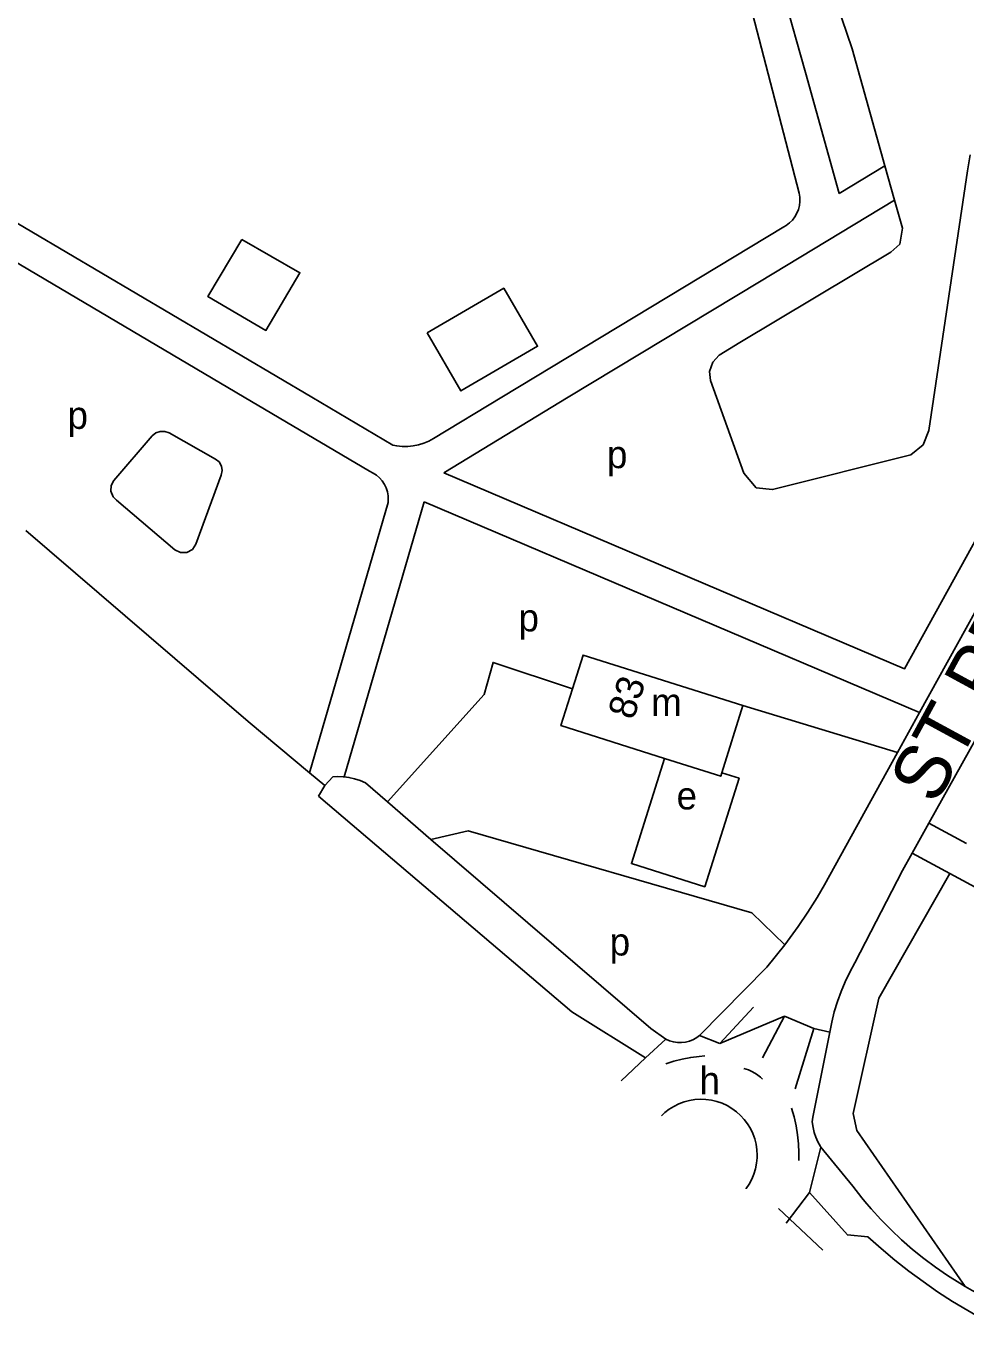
# Model space of a CAD drawing. Extents: x 162804 to 165059, y 381530 to 382901.
# Drawn here: x 163167.6 to 163304.5, y 381614.3 to 381804.1 of the extents above; entities that cross this region are included whole.
import ezdxf

# ---------------------------------------------------------------- set-up
doc = ezdxf.new("R2010")
doc.units = 0
for name, color, linetype in [('BLT_Basislijn', 7, 'Continuous'), ('BLT_Bebouwing', 7, 'Continuous'), ('BLT_Centroide', 7, 'Continuous'), ('BLT_Huisnummer', 7, 'Continuous'), ('BLT_Straatnaam_hoofdweg', 7, 'Continuous'), ('BLT_Vlakafsluiter', 7, 'Continuous')]:
    doc.layers.add(name, color=color, linetype=linetype)

msp = doc.modelspace()

# ---------------------------------------------------------------- linework, layer by layer
at = {"layer": 'BLT_Basislijn'}
for p, q in [((163269.68, 381838.14), (163279.75, 381802.12)), ((163280.18, 381779.7), (163265.55, 381836.33)), ((163279.75, 381802.12), (163281.1, 381797.3)), ((163281.1, 381797.3), (163286.03, 381779.66)), ((163148.62, 381785.81), (163209.2, 381750)), ((163292.69, 381783.69), (163286.03, 381779.66)), ((163292.69, 381783.69), (163294.09, 381778.69)), ((163146.08, 381781.51), (163199.38, 381750)), ((163294.09, 381778.69), (163274.43, 381766.82)), ((163277.97, 381774.82), (163236.9, 381750)), ((163274.43, 381766.82), (163246.57, 381750)), ((163199.38, 381750), (163217.63, 381739.21)), ((163209.2, 381750), (163221.04, 381743)), ((163236.9, 381750), (163226.94, 381743.99)), ((163246.57, 381750), (163228.44, 381738.97)), ((163297.74, 381704.09), (163318.64, 381741.96)), ((163220.33, 381734.65), (163208.89, 381695.28)), ((163225.56, 381734.76), (163213.93, 381694.7)), ((163199.95, 381702.79), (163167.55, 381730.6)), ((163316.35, 381718.94), (163299.08, 381687.95)), ((163271.98, 381705.1), (163294.51, 381698.24)), ((163294.51, 381698.24), (163297.74, 381704.09)), ((163199.95, 381702.79), (163208.89, 381695.28)), ((163283.87, 381678.96), (163294.51, 381698.24)), ((163208.89, 381695.28), (163211.1, 381693.42)), ((163212.26, 381694.71), (163211.1, 381693.42)), ((163220.22, 381691.07), (163217.03, 381693.81)), ((163211.1, 381693.42), (163210.2, 381691.87)), ((163226.57, 381685.6), (163220.22, 381691.07)), ((163299.08, 381687.95), (163296.65, 381683.58)), ((163299.08, 381687.95), (163304.57, 381685)), ((163296.65, 381683.58), (163302.14, 381680.63)), ((163302.14, 381680.63), (163291.79, 381662.45)), ((163302.14, 381680.63), (163307.1, 381677.96)), ((163275.49, 381666.96), (163278.12, 381670.25)), ((163265.68, 381657.02), (163275.49, 381666.96)), ((163291.79, 381662.45), (163288.06, 381645.69)), ((163273.55, 381661.15), (163268.65, 381655.86)), ((163278.07, 381659.86), (163274.84, 381653.79)), ((163282.32, 381658.05), (163279.62, 381649.27)), ((163284.65, 381657.53), (163282.2, 381645.14)), ((163261.26, 381646.29), (163260.62, 381645.79)), ((163261.95, 381646.71), (163261.26, 381646.29)), ((163262.67, 381647.07), (163261.95, 381646.71)), ((163263.43, 381647.36), (163262.67, 381647.07)), ((163264.21, 381647.56), (163263.43, 381647.36)), ((163265, 381647.7), (163264.21, 381647.56)), ((163265.81, 381647.74), (163265, 381647.7)), ((163266.62, 381647.72), (163265.81, 381647.74)), ((163267.42, 381647.61), (163266.62, 381647.72)), ((163268.2, 381647.42), (163267.42, 381647.61)), ((163268.97, 381647.16), (163268.2, 381647.42)), ((163269.7, 381646.82), (163268.97, 381647.16)), ((163270.4, 381646.41), (163269.7, 381646.82)), ((163271.05, 381645.93), (163270.4, 381646.41)), ((163260.62, 381645.79), (163260.15, 381645.35)), ((163271.65, 381645.4), (163271.05, 381645.93)), ((163272.2, 381644.8), (163271.65, 381645.4)), ((163272.68, 381644.15), (163272.2, 381644.8)), ((163282.2, 381645.14), (163282.1, 381644.44)), ((163288.06, 381645.69), (163288.59, 381643.17)), ((163273.1, 381643.46), (163272.68, 381644.15)), ((163273.45, 381642.73), (163273.1, 381643.46)), ((163273.72, 381641.97), (163273.45, 381642.73)), ((163288.59, 381643.17), (163304.39, 381620.46)), ((163273.92, 381641.19), (163273.72, 381641.97)), ((163274.04, 381640.39), (163273.92, 381641.19)), ((163283.36, 381640.75), (163288, 381635.07)), ((163274, 381638.41), (163274.07, 381639.22)), ((163274.08, 381639.59), (163274.04, 381640.39)), ((163274.07, 381639.22), (163274.08, 381639.59)), ((163273.3, 381636.1), (163273.61, 381636.85)), ((163273.61, 381636.85), (163273.84, 381637.62)), ((163273.84, 381637.62), (163274, 381638.41)), ((163272.47, 381634.72), (163272.92, 381635.39)), ((163272.92, 381635.39), (163273.3, 381636.1)), ((163272.46, 381634.7), (163272.47, 381634.72)), ((163277.16, 381631.84), (163283.62, 381625.78))]:
    msp.add_line(p, q, dxfattribs=at)
for points in [[(163285.66, 381807.29), (163287.92, 381800.74), (163292.69, 381783.69)], [(163294.09, 381778.69), (163295.22, 381774.64), (163294.83, 381772.31), (163293.55, 381771.11), (163271.56, 381757.97), (163268.52, 381756.15), (163267.6, 381755.11), (163267.13, 381753.75), (163267.28, 381752.42), (163272.13, 381738.94), (163273.95, 381736.81), (163276.33, 381736.55), (163296.44, 381741.63), (163298.25, 381743.08), (163299.1, 381745.15), (163304.71, 381782.98), (163305.09, 381785.3)], [(163228.44, 381738.97), (163295.54, 381710.45), (163314.26, 381744.38), (163334.75, 381781.49)], [(163280.18, 381779.7), (163280.28, 381779.12), (163280.29, 381778.52), (163280.23, 381777.93), (163280.08, 381777.35), (163279.86, 381776.8), (163279.57, 381776.28), (163279.21, 381775.81), (163278.79, 381775.39), (163278.32, 381775.03), (163277.97, 381774.82)], [(163226.94, 381743.99), (163226.24, 381743.6), (163225.51, 381743.29), (163224.75, 381743.06), (163223.97, 381742.9), (163223.18, 381742.82), (163222.38, 381742.82), (163221.59, 381742.9), (163221.04, 381743)], [(163217.63, 381739.21), (163218.16, 381738.96), (163218.65, 381738.63), (163219.09, 381738.25), (163219.48, 381737.8), (163219.8, 381737.31), (163220.06, 381736.78), (163220.24, 381736.22), (163220.34, 381735.64), (163220.36, 381735.05), (163220.33, 381734.65)], [(163225.56, 381734.76), (163297.74, 381704.09)], [(163247.18, 381707.51), (163235.61, 381711.37), (163234.32, 381706.72), (163220.22, 381691.07)], [(163260.59, 381697.37), (163255.76, 381682.07), (163266.45, 381678.7), (163271.44, 381694.51), (163268.93, 381695.28)], [(163213.93, 381694.7), (163213.78, 381694.72), (163212.94, 381694.75), (163212.26, 381694.71)], [(163217.03, 381693.81), (163216.26, 381694.15), (163215.45, 381694.42), (163214.62, 381694.61), (163213.93, 381694.7)], [(163210.2, 381691.87), (163247.1, 381660.5), (163257.81, 381653.79)], [(163226.57, 381685.6), (163232.01, 381686.84), (163273.29, 381674.89), (163278.12, 381670.25)], [(163260.78, 381656.5), (163258.58, 381658.05), (163226.57, 381685.6)], [(163296.65, 381683.58), (163295.23, 381681.05), (163288.32, 381667.59)], [(163278.12, 381670.25), (163280.06, 381672.91), (163281.46, 381674.99), (163282.79, 381677.11), (163283.87, 381678.96)], [(163288.32, 381667.59), (163287.57, 381666.24), (163286.9, 381664.85), (163286.29, 381663.42), (163285.76, 381661.97), (163285.31, 381660.49), (163284.93, 381658.99), (163284.65, 381657.53)], [(163257.81, 381653.79), (163260.78, 381656.5)], [(163260.78, 381656.5), (163261.32, 381656.26), (163261.89, 381656.09), (163262.47, 381656), (163263.07, 381655.99), (163263.65, 381656.06), (163264.23, 381656.21), (163264.78, 381656.43), (163265.29, 381656.73), (163265.68, 381657.02)], [(163260.78, 381652.89), (163261.96, 381653.28), (163263.17, 381653.59), (163264.4, 381653.83), (163265.64, 381653.99), (163266.45, 381654.05)], [(163272.13, 381652.24), (163272.79, 381652.03), (163273.41, 381651.74), (163274, 381651.39), (163274.55, 381650.97), (163274.84, 381650.69)], [(163279.1, 381646.43), (163279.47, 381645.16), (163279.76, 381643.87), (163279.97, 381642.57), (163280.1, 381641.25), (163280.15, 381639.93), (163280.13, 381638.82)], [(163282.1, 381644.44), (163282.24, 381643.65), (163282.39, 381642.92), (163282.61, 381642.21), (163282.91, 381641.52), (163283.28, 381640.87), (163283.36, 381640.75)], [(163283.36, 381640.75), (163281.68, 381634.17)], [(163288, 381635.07), (163289.31, 381633.4), (163289.77, 381632.86)], [(163281.68, 381634.17), (163287.23, 381627.97), (163290.2, 381627.71)], [(163289.77, 381632.86), (163290.67, 381631.79), (163292.1, 381630.22), (163293.58, 381628.72), (163295.12, 381627.27), (163296.71, 381625.87), (163298.36, 381624.54), (163300.05, 381623.27), (163301.79, 381622.07), (163303.58, 381620.93), (163304.39, 381620.46)], [(163290.2, 381627.71), (163292.13, 381625.99), (163294.11, 381624.32), (163296.15, 381622.72), (163298.23, 381621.18), (163300.36, 381619.7), (163302.53, 381618.29), (163304.75, 381616.95), (163307.01, 381615.68), (163309.3, 381614.48), (163309.68, 381614.29)], [(163304.39, 381620.46), (163305.4, 381619.87), (163307.27, 381618.87), (163309.17, 381617.94), (163310.71, 381617.26)]]:
    msp.add_lwpolyline(points, dxfattribs=at)
for points in [[(163199.04, 381772.98), (163207.49, 381768.14), (163202.54, 381759.72), (163194.08, 381764.66)], [(163226.02, 381759.38), (163237.18, 381765.87), (163242.1, 381757.42), (163230.94, 381750.92)], [(163180.36, 381737.86), (163185.99, 381744.39), (163186.52, 381744.79), (163187.13, 381745.01), (163187.82, 381745.02), (163188.42, 381744.83), (163195.2, 381740.99), (163195.71, 381740.57), (163196.05, 381739.98), (163196.16, 381739.31), (163196.03, 381738.66), (163192.33, 381728.61), (163191.82, 381727.84), (163191, 381727.39), (163190.1, 381727.37), (163189.25, 381727.79), (163180.78, 381735), (163180.27, 381735.51), (163179.94, 381736.34), (163179.99, 381737.14)]]:
    msp.add_lwpolyline(points, close=True, dxfattribs=at)
at = {"layer": 'BLT_Bebouwing'}
msp.add_line((163268.93, 381695.28), (163271.98, 381705.1), dxfattribs=at)
for points in [[(163271.98, 381705.1), (163248.72, 381712.43), (163247.18, 381707.51)], [(163247.18, 381707.51), (163245.49, 381702.16), (163260.59, 381697.37)], [(163260.59, 381697.37), (163268.78, 381694.8), (163268.93, 381695.28)]]:
    msp.add_lwpolyline(points, dxfattribs=at)
at = {"layer": 'BLT_Vlakafsluiter'}
for p, q in [((163268.65, 381655.86), (163278.07, 381659.86)), ((163278.07, 381659.86), (163282.32, 381658.05)), ((163282.32, 381658.05), (163284.65, 381657.53)), ((163265.68, 381657.02), (163268.65, 381655.86)), ((163254.28, 381650.42), (163257.81, 381653.79)), ((163272.47, 381634.72), (163272.47, 381634.69)), ((163281.68, 381634.17), (163278.28, 381629.67))]:
    msp.add_line(p, q, dxfattribs=at)

# ---------------------------------------------------------------- texts
at = {"layer": 'BLT_Centroide'}
for s, p in [('p', (163173.64, 381745.39)), ('p', (163252.2, 381739.67)), ('p', (163239.32, 381715.89)), ('m', (163258.64, 381703.59)), ('e', (163262.34, 381689.96)), ('p', (163252.6, 381668.68)), ('h', (163265.68, 381648.48))]:
    msp.add_text(s, height=4, dxfattribs=at).set_placement(p)
at = {"layer": 'BLT_Huisnummer'}
msp.add_text('83', height=4, rotation=72.506, dxfattribs=at).set_placement((163256.07, 381702.87))
at = {"layer": 'BLT_Straatnaam_hoofdweg'}
msp.add_text('ST PETRUS CANISIUSLAAN', height=8, rotation=61.4841, dxfattribs=at).set_placement((163300.05, 381690.41))

doc.saveas('drawing.dxf')
